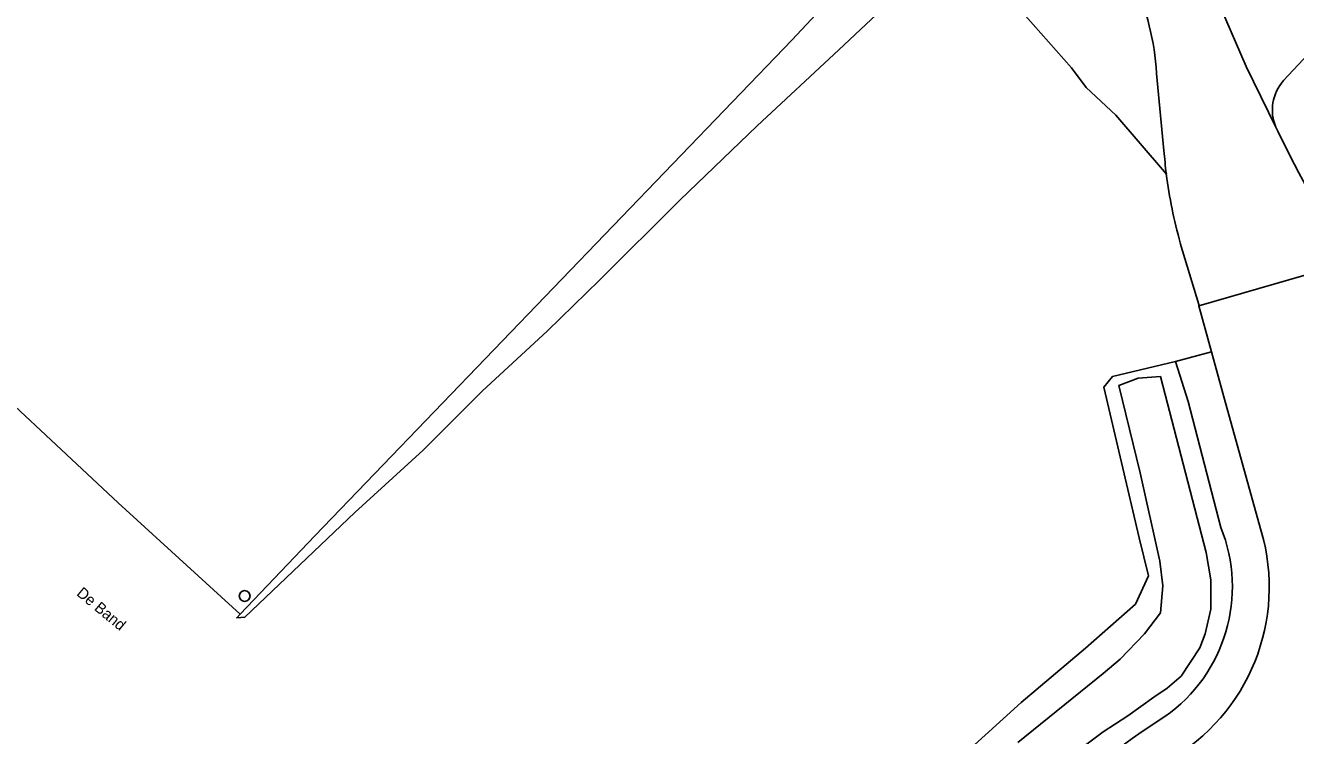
# Model space of a CAD drawing. Extents: x 156141 to 158132, y 385651 to 388333.
# Drawn here: x 156469.7 to 156584.7, y 387058.2 to 387122.4 of the extents above; entities that cross this region are included whole.
import ezdxf

# ---------------------------------------------------------------- set-up
doc = ezdxf.new("R2010")
doc.units = 0
for name, color, linetype in [('IMGEO_Berm_groen', 7, 'Continuous'), ('IMGEO_Boom', 7, 'Continuous'), ('IMGEO_Bouwland', 7, 'Continuous'), ('IMGEO_Groenvoorziening', 7, 'Continuous'), ('IMGEO_Oever', 7, 'Continuous'), ('IMGEO_Openbare_ruimte_label', 7, 'Continuous'), ('IMGEO_Rijbaan_lokaal_gesloten', 7, 'Continuous'), ('IMGEO_Rijbaan_lokaal_open', 7, 'Continuous'), ('IMGEO_Waterloop', 7, 'Continuous')]:
    doc.layers.add(name, color=color, linetype=linetype)

msp = doc.modelspace()

# ---------------------------------------------------------------- linework, layer by layer
at = {"layer": 'IMGEO_Berm_groen'}
for points in [[(156588.1, 387122.21), (156583.61, 387117.41)], [(156582.9, 387113.2), (156583.08, 387112.85)]]:
    msp.add_lwpolyline(points, dxfattribs=at)
for centre, radius, start, end in [((156586.55, 387114.76), 3.96, 137.9303, 203.1009), ((156749.31, 387195.34), 185.58, 206.3923, 210.5711)]:
    msp.add_arc(centre, radius, start, end, dxfattribs=at)
at = {"layer": 'IMGEO_Boom'}
msp.add_circle((156489.55, 387070.79), 0.489, dxfattribs=at)
at = {"layer": 'IMGEO_Bouwland'}
msp.add_lwpolyline([(156459.33, 387096.7), (156462.65, 387093.62), (156478.1, 387079.21), (156489.15, 387069.16), (156495.9, 387076.24), (156539.11, 387121.1), (156561.95, 387145.57), (156561.38, 387146.12), (156509.14, 387191.33), (156500, 387199.25), (156497.9, 387201.06), (156496.84, 387201.97), (156494.35, 387204.13), (156418.22, 387134.43), (156447.67, 387107.52)], close=True, dxfattribs=at)
at = {"layer": 'IMGEO_Groenvoorziening'}
for points in [[(156561.95, 387145.57), (156539.11, 387121.1), (156495.9, 387076.24), (156489.15, 387069.16), (156488.83, 387068.83), (156489.58, 387068.88), (156499.52, 387078.34), (156505.7, 387083.97), (156511.04, 387089.31), (156516.96, 387094.78), (156521.69, 387099.36), (156528.96, 387106.61), (156535.95, 387113.31), (156543.33, 387120.2), (156549.2, 387125.71)], [(156557.46, 387126.43), (156564.4, 387118.57), (156565.73, 387116.78), (156568.42, 387114.3), (156572.84, 387109.16), (156572.99, 387108.97)], [(156572.99, 387108.97), (156572.84, 387109.16), (156568.42, 387114.3), (156565.73, 387116.78), (156564.4, 387118.57), (156557.46, 387126.43)], [(156549.2, 387125.71), (156543.33, 387120.2), (156535.95, 387113.31), (156528.96, 387106.61), (156521.69, 387099.36), (156516.96, 387094.78), (156511.04, 387089.31), (156505.7, 387083.97), (156499.52, 387078.34), (156489.58, 387068.88), (156488.83, 387068.83), (156489.15, 387069.16), (156478.1, 387079.21), (156462.65, 387093.62)], [(156572.77, 387111.1), (156572.1, 387118.07)], [(156553.32, 387055.26), (156559.85, 387061.16), (156565.66, 387066.07), (156570.2, 387070.06), (156571.38, 387072.6), (156570.52, 387076.05), (156567.34, 387089.67), (156568.11, 387090.64), (156573.83, 387091.99), (156577.08, 387092.89), (156575.94, 387097.05), (156575.92, 387097.15), (156574.26, 387102.72)], [(156581.36, 387077.41), (156578.11, 387089.13), (156577.08, 387092.89), (156573.83, 387091.99), (156574.96, 387088.37), (156577.92, 387077)]]:
    msp.add_lwpolyline(points, dxfattribs=at)
for centre, radius, start, end in [((156549.53, 387116.81), 22.61, 3.202, 25.2877), ((156615.01, 387114.36), 42.36, 184.4221, 187.3186), ((156616.11, 387114.48), 43.47, 187.2851, 195.691), ((156564.62, 387071.63), 14.35, 305.0977, 21.9757), ((156564.24, 387071.6), 18.07, 302.0897, 18.7412), ((156611.6, 386999.19), 72.01, 122.5437, 131.6204)]:
    msp.add_arc(centre, radius, start, end, dxfattribs=at)
at = {"layer": 'IMGEO_Oever'}
for points in [[(156577.92, 387077), (156574.96, 387088.37), (156573.83, 387091.99), (156568.11, 387090.64), (156567.34, 387089.67), (156570.52, 387076.05), (156571.38, 387072.6), (156570.2, 387070.06), (156565.66, 387066.07), (156559.85, 387061.16), (156553.32, 387055.26)], [(156559.54, 387057.53), (156567.27, 387063.77), (156568.82, 387065.09), (156571.02, 387067.38), (156572.45, 387069.27), (156572.67, 387071.72), (156572.4, 387073.94), (156570.63, 387081.93), (156568.68, 387089.83), (156570.45, 387090.51), (156572.45, 387090.64), (156576.6, 387074.73), (156577.01, 387072.24), (156577.03, 387069.61), (156576.51, 387067.38), (156576.03, 387066.09), (156574.35, 387063.55), (156573.08, 387062.46), (156571.86, 387061.64), (156569.5, 387059.96), (156567.27, 387058.51), (156565.59, 387057.24)]]:
    msp.add_lwpolyline(points, dxfattribs=at)
for centre, radius, start, end in [((156564.62, 387071.63), 14.35, 305.0977, 21.9757), ((156611.6, 386999.19), 72.01, 122.5437, 131.6204)]:
    msp.add_arc(centre, radius, start, end, dxfattribs=at)
at = {"layer": 'IMGEO_Rijbaan_lokaal_gesloten'}
for points in [[(156583.08, 387112.85), (156582.9, 387113.2), (156580.23, 387118.69), (156577.9, 387124.05), (156577.65, 387124.61), (156572.76, 387136.51), (156571.61, 387139.46), (156572.35, 387140.15), (156570.41, 387141.92), (156572.52, 387144.73), (156567.88, 387148.86), (156564.22, 387152.44), (156553.74, 387161.94), (156536.86, 387176.5), (156531.73, 387180.93), (156531.35, 387181.26), (156524.83, 387186.88), (156513.6, 387196.57), (156454.46, 387247.59), (156447.68, 387253.43), (156441.89, 387258.43), (156419.06, 387278.12), (156395.19, 387298.72)], [(156572.1, 387118.07), (156572.77, 387111.1)], [(156574.26, 387102.72), (156575.92, 387097.15), (156575.94, 387097.05), (156589.53, 387100.96)], [(156595.63, 387079.03), (156592.85, 387089.08), (156592.17, 387091.49), (156589.58, 387100.85), (156589.53, 387100.96), (156575.94, 387097.05), (156577.08, 387092.89), (156578.11, 387089.13), (156581.36, 387077.41)]]:
    msp.add_lwpolyline(points, dxfattribs=at)
for centre, radius, start, end in [((156549.53, 387116.81), 22.61, 3.202, 25.2877), ((156749.31, 387195.34), 185.58, 206.3923, 210.5711), ((156615.01, 387114.36), 42.36, 184.4221, 187.3186), ((156616.11, 387114.48), 43.47, 187.2851, 195.691), ((156564.24, 387071.6), 18.07, 302.0897, 18.7412)]:
    msp.add_arc(centre, radius, start, end, dxfattribs=at)
at = {"layer": 'IMGEO_Rijbaan_lokaal_open'}
for points in [[(156577.9, 387124.05), (156580.23, 387118.69), (156582.9, 387113.2)], [(156583.61, 387117.41), (156588.1, 387122.21)]]:
    msp.add_lwpolyline(points, dxfattribs=at)
msp.add_arc((156586.55, 387114.76), 3.96, 137.9303, 203.1009, dxfattribs=at)
at = {"layer": 'IMGEO_Waterloop'}
msp.add_lwpolyline([(156565.59, 387057.24), (156567.27, 387058.51), (156569.5, 387059.96), (156571.86, 387061.64), (156573.08, 387062.46), (156574.35, 387063.55), (156576.03, 387066.09), (156576.51, 387067.38), (156577.03, 387069.61), (156577.01, 387072.24), (156576.6, 387074.73), (156572.45, 387090.64), (156570.45, 387090.51), (156568.68, 387089.83), (156570.63, 387081.93), (156572.4, 387073.94), (156572.67, 387071.72), (156572.45, 387069.27), (156571.02, 387067.38), (156568.82, 387065.09), (156567.27, 387063.77), (156559.54, 387057.53)], dxfattribs=at)

# ---------------------------------------------------------------- texts
at = {"layer": 'IMGEO_Openbare_ruimte_label'}
msp.add_text('De Band', height=1, rotation=320.3558, dxfattribs=at).set_placement((156474.26, 387070.91))

doc.saveas('drawing.dxf')
